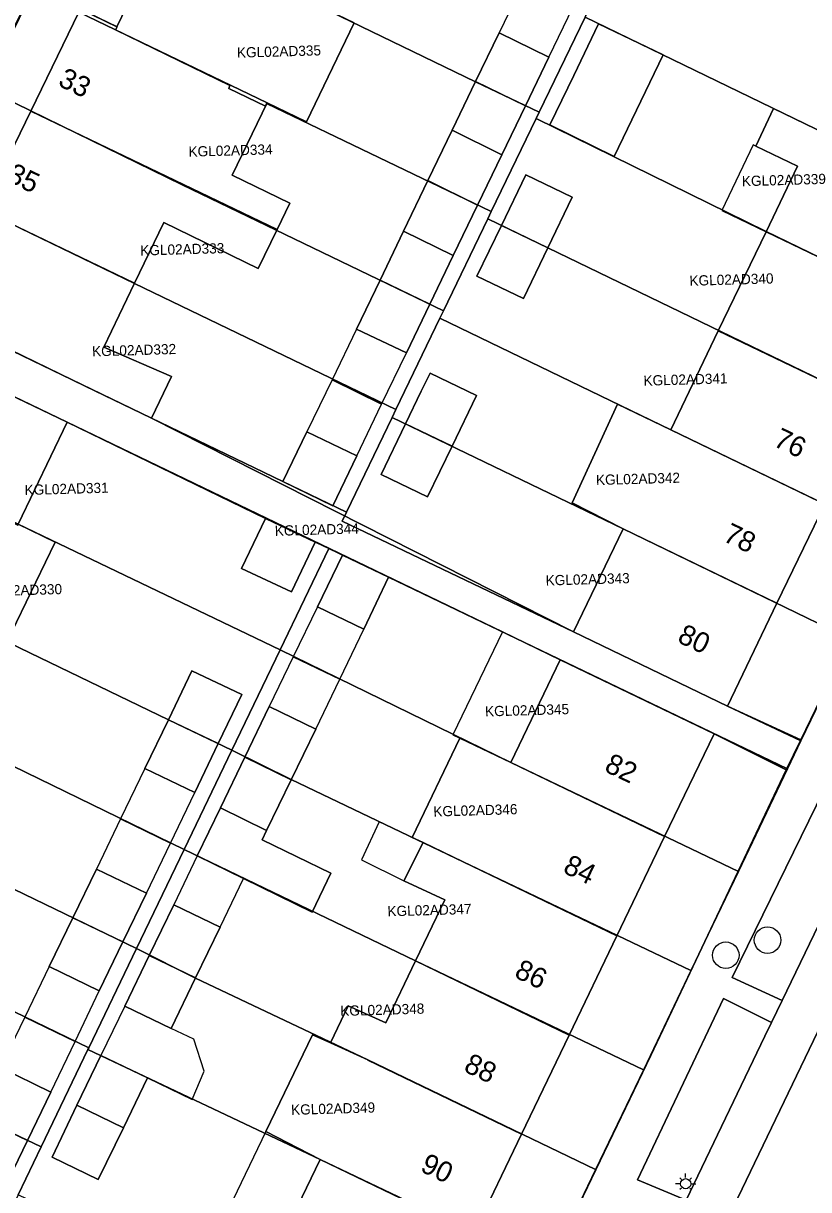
# Model space of a CAD drawing. Extents: x 124901 to 125496, y 515369 to 515789.
# Drawn here: x 125295 to 125333.5, y 515460.9 to 515518 of the extents above; entities that cross this region are included whole.
import ezdxf

# ---------------------------------------------------------------- set-up
doc = ezdxf.new("R2010")
doc.units = 0
for name, color, linetype in [('Gebouw', 7, 'Continuous'), ('Lichtmast', 7, 'Continuous'), ('Luifel', 7, 'Continuous'), ('Onbegroeid terrein', 7, 'Continuous'), ('Parkeren', 7, 'Continuous'), ('Perceelnummers', 7, 'Continuous'), ('Perceelsgrenzen', 7, 'Continuous'), ('Putten', 7, 'Continuous'), ('Teksten', 7, 'Continuous'), ('Vegetatie', 7, 'Continuous'), ('Voetpad', 7, 'Continuous'), ('Wegen lokale weg', 7, 'Continuous')]:
    doc.layers.add(name, color=color, linetype=linetype)

msp = doc.modelspace()

# ---------------------------------------------------------------- linework, layer by layer
at = {"layer": 'Gebouw'}
for points in [[(125311.242, 515518.066), (125301.872, 515522.573), (125299.598, 515517.871), (125297.8, 515518.74), (125297.724, 515518.583), (125306.962, 515514.145), (125308.903, 515513.213)], [(125307.452, 515507.927), (125308.082, 515509.226), (125305.243, 515510.606), (125306.962, 515514.145), (125297.724, 515518.583), (125295.363, 515513.735)], [(125323.23, 515518.02), (125322.01, 515515.49), (125320.838, 515513.074), (125323.997, 515511.516), (125326.396, 515516.492)], [(125319.64, 515513.995), (125320.79, 515516.39), (125318.35, 515517.58), (125317.195, 515515.19)], [(125316.04, 515512.8), (125318.49, 515511.6), (125319.64, 515513.995), (125317.195, 515515.19)], [(125295.363, 515513.735), (125292.998, 515508.888), (125300.457, 515505.304), (125301.897, 515508.27), (125306.527, 515506.022), (125307.452, 515507.927)], [(125341.43, 515509.24), (125333.87, 515512.87), (125331.805, 515513.862), (125330.944, 515512.016), (125332.989, 515511.034), (125331.449, 515507.827), (125339.003, 515504.198)], [(125318.49, 515511.6), (125316.04, 515512.8), (125314.853, 515510.331), (125317.295, 515509.13)], [(125313.66, 515507.85), (125316.1, 515506.66), (125317.295, 515509.13), (125314.853, 515510.331)], [(125320.74, 515507.03), (125321.93, 515509.52), (125319.66, 515510.61), (125318.46, 515508.13)], [(125292.998, 515508.888), (125290.55, 515503.87), (125301.294, 515498.685), (125302.273, 515500.732), (125298.949, 515502.171), (125300.457, 515505.304)], [(125320.74, 515507.03), (125318.46, 515508.13), (125317.26, 515505.65), (125319.54, 515504.55)], [(125312.505, 515505.45), (125314.95, 515504.275), (125316.1, 515506.66), (125313.66, 515507.85)], [(125336.663, 515499.337), (125339.003, 515504.198), (125331.449, 515507.827), (125329.105, 515502.969)], [(125314.95, 515504.275), (125312.505, 515505.45), (125311.35, 515503.05), (125313.8, 515501.89)], [(125336.663, 515499.337), (125329.105, 515502.969), (125326.77, 515498.11), (125334.327, 515494.474)], [(125287.319, 515497.008), (125294.729, 515493.436), (125294.75, 515493.48), (125297.16, 515498.48), (125289.74, 515502.04)], [(125316.04, 515497.305), (125317.24, 515499.79), (125314.96, 515500.89), (125314.531, 515500), (125313.762, 515498.408)], [(125334.327, 515494.474), (125326.77, 515498.11), (125324.164, 515499.364), (125321.928, 515494.535), (125324.43, 515493.25), (125331.982, 515489.616)], [(125316.04, 515497.305), (125313.762, 515498.408), (125312.56, 515495.92), (125314.84, 515494.82)], [(125308.92, 515498.01), (125307.74, 515495.57), (125310.19, 515494.39), (125311.37, 515496.84)], [(125294.199, 515487.707), (125296.559, 515492.595), (125294.75, 515493.48), (125294.729, 515493.436), (125287.319, 515497.008), (125284.984, 515492.149)], [(125308.16, 515490.16), (125309.33, 515492.61), (125306.88, 515493.77), (125305.7, 515491.32)], [(125331.982, 515489.616), (125324.43, 515493.25), (125322, 515488.21), (125329.56, 515484.57)], [(125311.71, 515488.33), (125312.92, 515490.89), (125310.66, 515491.97), (125309.43, 515489.43)], [(125302.12, 515483.89), (125304.57, 515482.73), (125305.72, 515485.13), (125303.27, 515486.29)], [(125326.467, 515478.164), (125328.9, 515483.21), (125321.35, 515486.84), (125318.919, 515481.798)], [(125307.07, 515484.54), (125305.87, 515482.06), (125308.145, 515480.955), (125309.35, 515483.44)], [(125303.42, 515480.33), (125304.57, 515482.73), (125302.12, 515483.89), (125300.96, 515481.5)], [(125324.129, 515473.297), (125326.467, 515478.164), (125318.919, 515481.798), (125316.426, 515482.998), (125314.087, 515478.13), (125314.614, 515477.876), (125316.58, 515476.93)], [(125304.67, 515479.58), (125306.94, 515478.47), (125308.145, 515480.955), (125305.87, 515482.06)], [(125306.94, 515478.47), (125304.67, 515479.58), (125303.535, 515477.221), (125305.807, 515476.11), (125309.176, 515474.463), (125310.09, 515476.367), (125306.721, 515478.015)], [(125324.129, 515473.297), (125316.58, 515476.93), (125314.614, 515477.876), (125313.669, 515476.003), (125315.686, 515475.073), (125314.239, 515472.068), (125321.787, 515468.433)], [(125299.885, 515473), (125301.04, 515475.4), (125298.59, 515476.57), (125297.43, 515474.18)], [(125302.38, 515474.82), (125301.18, 515472.335), (125303.455, 515471.235), (125304.66, 515473.72)], [(125299.885, 515473), (125297.43, 515474.18), (125296.27, 515471.79), (125298.73, 515470.6)], [(125302.25, 515468.75), (125303.455, 515471.235), (125301.18, 515472.335), (125299.98, 515469.85)], [(125311.901, 515467.202), (125319.445, 515463.569), (125321.787, 515468.433), (125314.239, 515472.068), (125312.786, 515469.043), (125310.948, 515469.875), (125310.072, 515468.053), (125311.91, 515467.22)], [(125317.107, 515458.702), (125319.445, 515463.569), (125311.901, 515467.202), (125311.91, 515467.22), (125310.072, 515468.053), (125309.191, 515468.452), (125306.908, 515463.71), (125309.56, 515462.33)], [(125297.63, 515464.99), (125299.91, 515463.89), (125301.089, 515466.339), (125298.813, 515467.437)], [(125293.89, 515466.84), (125292.74, 515464.44), (125295.2, 515463.27), (125296.36, 515465.64)], [(125298.67, 515461.36), (125299.91, 515463.89), (125297.63, 515464.99), (125296.41, 515462.45)], [(125292.74, 515464.44), (125291.59, 515462.04), (125294.05, 515460.87), (125295.2, 515463.27)], [(125317.107, 515458.702), (125309.56, 515462.33), (125307.13, 515457.29), (125314.169, 515453.906), (125314.68, 515453.66)]]:
    msp.add_lwpolyline(points, close=True, dxfattribs=at)
at = {"layer": 'Lichtmast'}
for p, q in [((125327.202, 515461.147), (125327.002, 515461.146)), ((125327.29, 515461.358), (125327.22, 515461.429)), ((125327.502, 515461.446), (125327.502, 515461.646)), ((125327.714, 515461.358), (125327.785, 515461.43)), ((125327.802, 515461.146), (125328.002, 515461.146)), ((125327.29, 515460.934), (125327.218, 515460.863)), ((125327.714, 515460.934), (125327.784, 515460.863))]:
    msp.add_line(p, q, dxfattribs=at)
msp.add_circle((125327.502, 515461.146), 0.25, dxfattribs=at)
at = {"layer": 'Luifel'}
for points in [[(125321.98, 515518.855), (125319.542, 515520.054), (125318.35, 515517.58), (125320.79, 515516.39)], [(125331.449, 515507.827), (125332.989, 515511.034), (125330.944, 515512.016), (125330.812, 515512.079), (125329.272, 515508.872)], [(125312.585, 515499.365), (125313.8, 515501.89), (125311.35, 515503.05), (125310.151, 515500.562)], [(125308.92, 515498.01), (125311.37, 515496.84), (125312.585, 515499.365), (125310.151, 515500.562)], [(125310.527, 515485.879), (125311.71, 515488.33), (125309.43, 515489.43), (125308.25, 515486.985)], [(125318.512, 515488.206), (125316.082, 515483.164), (125316.426, 515482.998), (125318.919, 515481.798), (125321.35, 515486.84)], [(125308.25, 515486.985), (125307.07, 515484.54), (125309.35, 515483.44), (125310.527, 515485.879)], [(125299.775, 515479.035), (125302.221, 515477.847), (125303.42, 515480.33), (125300.96, 515481.5)], [(125302.221, 515477.847), (125299.775, 515479.035), (125298.59, 515476.57), (125301.04, 515475.4)], [(125314.087, 515478.13), (125312.465, 515478.884), (125311.599, 515477.021), (125313.669, 515476.003), (125314.614, 515477.876)], [(125302.38, 515474.82), (125304.66, 515473.72), (125305.807, 515476.11), (125303.535, 515477.221)], [(125297.544, 515468.118), (125298.73, 515470.6), (125296.27, 515471.79), (125295.08, 515469.315)], [(125298.813, 515467.437), (125301.089, 515466.339), (125303.291, 515465.276), (125303.869, 515466.67), (125303.373, 515468.228), (125302.25, 515468.75), (125299.98, 515469.85)], [(125296.36, 515465.64), (125297.544, 515468.118), (125295.08, 515469.315), (125293.89, 515466.84)], [(125307.13, 515457.29), (125309.56, 515462.33), (125306.908, 515463.71), (125304.478, 515458.67)]]:
    msp.add_lwpolyline(points, close=True, dxfattribs=at)
at = {"layer": 'Onbegroeid terrein'}
for points in [[(125290.55, 515503.87), (125292.998, 515508.888), (125295.363, 515513.735), (125297.724, 515518.583), (125297.8, 515518.74), (125299.598, 515517.871), (125301.872, 515522.573), (125304.219, 515527.427), (125306.559, 515532.287), (125309, 515537.33), (125306.955, 515538.317), (125303.964, 515537.246), (125294.551, 515517.864), (125288.354, 515504.93)], [(125322.01, 515515.49), (125323.23, 515518.02), (125326.396, 515516.492), (125323.997, 515511.516), (125320.838, 515513.074)], [(125312.505, 515505.45), (125313.66, 515507.85), (125314.853, 515510.331), (125316.04, 515512.8), (125317.195, 515515.19), (125318.35, 515517.58), (125320.79, 515516.39), (125319.64, 515513.995), (125318.49, 515511.6), (125317.295, 515509.13), (125316.1, 515506.66), (125314.95, 515504.275), (125313.8, 515501.89), (125311.35, 515503.05)], [(125320.74, 515507.03), (125319.54, 515504.55), (125317.26, 515505.65), (125318.46, 515508.13), (125319.66, 515510.61), (125321.93, 515509.52)], [(125317.24, 515499.79), (125316.04, 515497.305), (125314.84, 515494.82), (125312.56, 515495.92), (125313.762, 515498.408), (125314.531, 515500), (125314.96, 515500.89)], [(125307.74, 515495.57), (125308.92, 515498.01), (125311.37, 515496.84), (125310.19, 515494.39)], [(125309.33, 515492.61), (125308.16, 515490.16), (125305.7, 515491.32), (125306.88, 515493.77)], [(125312.92, 515490.89), (125311.71, 515488.33), (125309.43, 515489.43), (125310.66, 515491.97)], [(125304.57, 515482.73), (125303.42, 515480.33), (125300.96, 515481.5), (125302.12, 515483.89), (125303.27, 515486.29), (125305.72, 515485.13)], [(125305.87, 515482.06), (125307.07, 515484.54), (125309.35, 515483.44), (125308.145, 515480.955), (125306.94, 515478.47), (125306.721, 515478.015), (125310.09, 515476.367), (125309.176, 515474.463), (125305.807, 515476.11), (125303.535, 515477.221), (125304.67, 515479.58)], [(125319.445, 515463.569), (125317.107, 515458.702), (125314.68, 515453.66), (125314.169, 515453.906), (125313.136, 515451.77), (125317.296, 515449.771), (125325.794, 515467.439), (125332.428, 515481.437), (125328.9, 515483.21), (125326.467, 515478.164), (125324.129, 515473.297), (125321.787, 515468.433)], [(125301.04, 515475.4), (125299.885, 515473), (125298.73, 515470.6), (125296.27, 515471.79), (125297.43, 515474.18), (125298.59, 515476.57)], [(125301.18, 515472.335), (125302.38, 515474.82), (125304.66, 515473.72), (125303.455, 515471.235), (125302.25, 515468.75), (125299.98, 515469.85)], [(125299.91, 515463.89), (125298.67, 515461.36), (125296.41, 515462.45), (125297.63, 515464.99), (125298.813, 515467.437), (125301.089, 515466.339)], [(125292.74, 515464.44), (125293.89, 515466.84), (125296.36, 515465.64), (125295.2, 515463.27), (125294.05, 515460.87), (125291.59, 515462.04)]]:
    msp.add_lwpolyline(points, close=True, dxfattribs=at)
for points in [[(125311.242, 515518.066), (125308.903, 515513.213), (125306.962, 515514.145), (125305.243, 515510.606), (125308.082, 515509.226), (125307.452, 515507.927), (125306.527, 515506.022), (125301.897, 515508.27), (125300.457, 515505.304), (125298.949, 515502.171), (125302.273, 515500.732), (125301.294, 515498.685), (125322, 515488.21), (125324.43, 515493.25), (125321.928, 515494.535), (125324.164, 515499.364), (125326.77, 515498.11), (125329.105, 515502.969), (125331.449, 515507.827), (125332.989, 515511.034), (125330.944, 515512.016), (125331.805, 515513.862), (125333.87, 515512.87)], [(125307.13, 515457.29), (125309.56, 515462.33), (125306.908, 515463.71), (125309.191, 515468.452), (125310.072, 515468.053), (125310.948, 515469.875), (125312.786, 515469.043), (125314.239, 515472.068), (125315.686, 515475.073), (125313.669, 515476.003), (125314.614, 515477.876), (125314.087, 515478.13), (125316.426, 515482.998), (125318.919, 515481.798), (125321.35, 515486.84), (125318.512, 515488.206), (125297.16, 515498.48), (125294.75, 515493.48), (125296.559, 515492.595), (125294.199, 515487.707)], [(125334.327, 515494.474), (125331.982, 515489.616), (125329.56, 515484.57), (125333.157, 515482.918), (125339.905, 515496.873)]]:
    msp.add_lwpolyline(points, dxfattribs=at)
at = {"layer": 'Parkeren'}
msp.add_lwpolyline([(125327.069, 515459.363), (125321.82, 515448.4), (125321.344, 515447.407), (125320.601, 515445.855), (125320.611, 515445.794), (125320.771, 515445.648), (125322.459, 515444.797), (125322.468, 515444.71), (125322.447, 515444.61), (125338.718, 515478.436), (125338.65, 515478.425), (125338.571, 515478.432), (125338.447, 515478.456), (125336.857, 515479.152), (125336.716, 515479.168), (125336.595, 515479.085), (125336.512, 515478.971), (125332.233, 515470.132), (125331.708, 515469.046), (125331.383, 515468.375), (125327.533, 515460.333)], close=True, dxfattribs=at)
at = {"layer": 'Perceelsgrenzen'}
for points in [[(125336.39, 515575.4), (125352.406, 515529.691), (125343.975, 515512.205), (125345.523, 515508.163), (125345.149, 515507.412), (125341.43, 515509.24), (125333.87, 515512.87), (125322.57, 515518.34), (125322.65, 515518.55), (125325, 515523.42), (125327.42, 515528.45), (125316.41, 515533.74), (125306.93, 515538.33), (125303.96, 515537.26), (125304.71, 515538.82), (125303.66, 515539.33), (125300.051, 515541.058), (125304.704, 515550.804), (125310.802, 515563.5)], [(125336.39, 515575.4), (125352.406, 515529.691), (125343.975, 515512.205), (125345.523, 515508.163), (125345.149, 515507.412), (125342.65, 515502.406), (125340.25, 515497.6), (125337.91, 515492.73), (125335.57, 515487.86), (125333.16, 515482.87), (125332.5, 515481.49), (125330.087, 515476.457), (125327.76, 515471.601), (125325.428, 515466.737), (125323.079, 515461.836), (125320.761, 515457)]]:
    msp.add_lwpolyline(points, dxfattribs=at)
for points in [[(125297.82, 515524.54), (125300.17, 515529.41), (125311.64, 515523.86), (125322.65, 515518.55), (125322.57, 515518.34), (125320.31, 515513.68), (125317.19, 515515.18), (125301.88, 515522.59)], [(125295.48, 515519.69), (125297.82, 515524.54), (125301.88, 515522.59), (125317.19, 515515.18), (125320.31, 515513.68), (125320.17, 515513.38), (125317.96, 515508.81), (125306.94, 515514.12), (125306.88, 515513.98), (125305.08, 515514.85), (125305.14, 515515), (125299.53, 515517.73), (125299.6, 515517.87), (125297.8, 515518.74), (125297.73, 515518.6)], [(125295.48, 515519.69), (125297.73, 515518.6), (125297.8, 515518.74), (125299.6, 515517.87), (125299.53, 515517.73), (125305.14, 515515), (125305.08, 515514.85), (125306.88, 515513.98), (125306.94, 515514.12), (125317.96, 515508.81), (125317.79, 515508.45), (125315.62, 515503.95), (125302.8, 515510.13), (125293.12, 515514.85)], [(125342.65, 515502.406), (125331.45, 515507.83), (125320.17, 515513.38), (125320.31, 515513.68), (125322.57, 515518.34), (125333.87, 515512.87), (125341.43, 515509.24), (125345.149, 515507.412)], [(125290.75, 515509.98), (125293.12, 515514.85), (125302.8, 515510.13), (125315.62, 515503.95), (125315.44, 515503.58), (125313.28, 515499.1), (125300.45, 515505.29)], [(125317.79, 515508.45), (125317.96, 515508.81), (125320.17, 515513.38), (125331.45, 515507.83), (125342.65, 515502.406), (125340.25, 515497.6), (125320.74, 515507.03)], [(125288.3, 515504.97), (125290.75, 515509.98), (125300.45, 515505.29), (125313.28, 515499.1), (125313.1, 515498.72), (125310.86, 515494.08), (125307.74, 515495.57), (125298.03, 515500.26)], [(125315.44, 515503.58), (125315.62, 515503.95), (125317.79, 515508.45), (125320.74, 515507.03), (125340.25, 515497.6), (125337.91, 515492.73), (125326.77, 515498.11)], [(125288.3, 515504.97), (125298.03, 515500.26), (125307.74, 515495.57), (125310.86, 515494.08), (125310.64, 515493.64), (125322, 515488.21), (125329.56, 515484.57), (125333.16, 515482.87), (125332.5, 515481.49), (125312.92, 515490.89), (125309.99, 515492.29), (125306.88, 515493.77), (125297.16, 515498.48), (125287.49, 515503.13)], [(125313.28, 515499.1), (125315.44, 515503.58), (125326.77, 515498.11), (125337.91, 515492.73), (125335.57, 515487.86), (125324.43, 515493.25), (125313.1, 515498.72)], [(125287.49, 515503.13), (125297.16, 515498.48), (125306.88, 515493.77), (125309.99, 515492.29), (125307.6, 515487.33), (125294.75, 515493.48), (125285.07, 515498.11)], [(125310.86, 515494.08), (125313.1, 515498.72), (125324.43, 515493.25), (125335.57, 515487.86), (125333.16, 515482.87), (125329.56, 515484.57), (125322, 515488.21), (125310.64, 515493.64)], [(125282.72, 515493.22), (125285.07, 515498.11), (125294.75, 515493.48), (125307.6, 515487.33), (125305.24, 515482.41), (125302.12, 515483.89), (125292.4, 515488.59)], [(125280.38, 515488.35), (125282.72, 515493.22), (125292.4, 515488.59), (125302.12, 515483.89), (125305.24, 515482.41), (125302.89, 515477.54), (125291.87, 515482.89), (125291.94, 515483.03), (125290.14, 515483.89), (125290.07, 515483.75), (125284.42, 515486.41), (125284.35, 515486.26), (125282.56, 515487.12), (125282.63, 515487.27)], [(125307.6, 515487.33), (125309.99, 515492.29), (125312.92, 515490.89), (125332.5, 515481.49), (125330.087, 515476.457), (125318.92, 515481.8)], [(125278.04, 515483.5), (125280.38, 515488.35), (125282.63, 515487.27), (125282.56, 515487.12), (125284.35, 515486.26), (125284.42, 515486.41), (125290.07, 515483.75), (125290.14, 515483.89), (125291.94, 515483.03), (125291.87, 515482.89), (125302.89, 515477.54), (125300.55, 515472.68), (125289.52, 515478), (125282.09, 515481.55)], [(125305.24, 515482.41), (125307.6, 515487.33), (125318.92, 515481.8), (125330.087, 515476.457), (125327.76, 515471.601), (125316.58, 515476.93), (125308.15, 515480.96)], [(125278.04, 515483.5), (125282.09, 515481.55), (125289.52, 515478), (125300.55, 515472.68), (125298.21, 515467.81), (125287.19, 515473.14), (125275.7, 515478.62)], [(125302.89, 515477.54), (125305.24, 515482.41), (125308.15, 515480.96), (125316.58, 515476.93), (125327.76, 515471.601), (125325.428, 515466.737), (125314.24, 515472.07)], [(125295.87, 515462.95), (125292.74, 515464.44), (125287.76, 515466.88), (125277.42, 515471.81), (125273.36, 515473.76), (125275.7, 515478.62), (125287.19, 515473.14), (125298.21, 515467.81), (125298.17, 515467.726)], [(125300.55, 515472.68), (125302.89, 515477.54), (125314.24, 515472.07), (125325.428, 515466.737), (125323.079, 515461.836), (125311.909, 515467.218), (125303.45, 515471.23)], [(125295.87, 515462.95), (125294.746, 515460.609), (125293.45, 515457.91), (125282.44, 515463.26), (125270.96, 515468.75), (125273.36, 515473.76), (125277.42, 515471.81), (125287.76, 515466.88), (125292.74, 515464.44)], [(125298.21, 515467.81), (125300.55, 515472.68), (125303.45, 515471.23), (125311.909, 515467.218), (125323.079, 515461.836), (125320.761, 515457), (125309.561, 515462.333), (125298.17, 515467.726)], [(125295.87, 515462.95), (125298.17, 515467.726), (125309.561, 515462.333), (125320.761, 515457), (125317.296, 515449.771), (125294.746, 515460.609)]]:
    msp.add_lwpolyline(points, close=True, dxfattribs=at)
at = {"layer": 'Putten'}
for centre in [(125331.52, 515473.09), (125329.47, 515472.35)]:
    msp.add_circle(centre, 0.65, dxfattribs=at)
at = {"layer": 'Vegetatie'}
for points in [[(125332.233, 515470.132), (125336.512, 515478.971), (125336.595, 515479.085), (125336.716, 515479.168), (125336.857, 515479.152), (125334.303, 515480.479), (125329.781, 515471.259)], [(125327.533, 515460.333), (125331.383, 515468.375), (125331.708, 515469.046), (125329.36, 515470.225), (125325.141, 515461.339)]]:
    msp.add_lwpolyline(points, close=True, dxfattribs=at)
at = {"layer": 'Voetpad'}
msp.add_lwpolyline([(125332.428, 515481.437), (125333.157, 515482.918), (125329.56, 515484.57), (125322, 515488.21), (125301.294, 515498.685), (125290.55, 515503.87), (125288.354, 515504.93), (125287.492, 515503.125), (125289.74, 515502.04), (125297.16, 515498.48), (125318.512, 515488.206), (125321.35, 515486.84), (125328.9, 515483.21)], close=True, dxfattribs=at)
for points in [[(125339.905, 515496.873), (125333.157, 515482.918), (125332.428, 515481.437), (125325.794, 515467.439), (125317.296, 515449.771)], [(125327.533, 515460.333), (125325.141, 515461.339), (125329.36, 515470.225), (125331.708, 515469.046), (125332.233, 515470.132), (125329.781, 515471.259), (125334.303, 515480.479)]]:
    msp.add_lwpolyline(points, dxfattribs=at)
at = {"layer": 'Wegen lokale weg'}
msp.add_lwpolyline([(125323.653, 515432.831), (125327.735, 515441.596), (125330.916, 515448.196), (125333.443, 515453.439), (125340.998, 515469.097), (125347.883, 515483.449), (125350.047, 515487.919), (125354.111, 515496.359), (125348.614, 515499.006), (125346.984, 515495.648), (125339.36, 515479.68), (125338.718, 515478.436), (125322.447, 515444.61)], dxfattribs=at)

# ---------------------------------------------------------------- texts
at = {"layer": 'Perceelnummers'}
for s, rotation, p in [('KGL02AD335', 1.6334, (125305.491, 515516.356)), ('KGL02AD334', 1.6334, (125303.115, 515511.501)), ('KGL02AD339', 1.6337, (125330.267, 515510.054)), ('KGL02AD333', 1.6334, (125300.746, 515506.656)), ('KGL02AD340', 1.6337, (125327.695, 515505.171)), ('KGL02AD332', 1.6333, (125298.382, 515501.711)), ('KGL02AD341', 1.6337, (125325.44, 515500.271)), ('KGL02AD342', 1.6336, (125323.108, 515495.401)), ('KGL02AD331', 1.6333, (125295.071, 515494.911)), ('KGL02AD344', 1.6335, (125307.348, 515492.911)), ('KGL02AD343', 1.6336, (125320.639, 515490.476)), ('KGL02AD330', 1.6333, (125292.785, 515489.941)), ('KGL02AD345', 1.6336, (125317.664, 515484.055)), ('KGL02AD346', 1.6335, (125315.129, 515479.147)), ('KGL02AD347', 1.6335, (125312.876, 515474.255)), ('KGL02AD348', 1.6335, (125310.561, 515469.369)), ('KGL02AD349', 1.6335, (125308.147, 515464.521))]:
    msp.add_text(s, height=0.5, rotation=rotation, dxfattribs=at).set_placement(p)
at = {"layer": 'Teksten'}
for s, rotation, p in [('33', 334, (125296.654, 515515.013)), ('35', 334, (125294.138, 515510.336)), ('76', 334.3, (125331.751, 515497.346)), ('78', 334.2, (125329.283, 515492.686)), ('80', 334.4, (125327.041, 515487.731)), ('82', 334.3, (125323.461, 515481.394)), ('84', 334.3, (125321.428, 515476.428)), ('86', 334.3, (125319.041, 515471.298)), ('88', 334.3, (125316.558, 515466.684)), ('90', 334.3, (125314.428, 515461.781))]:
    msp.add_text(s, height=1, rotation=rotation, dxfattribs=at).set_placement(p)

doc.saveas('drawing.dxf')
